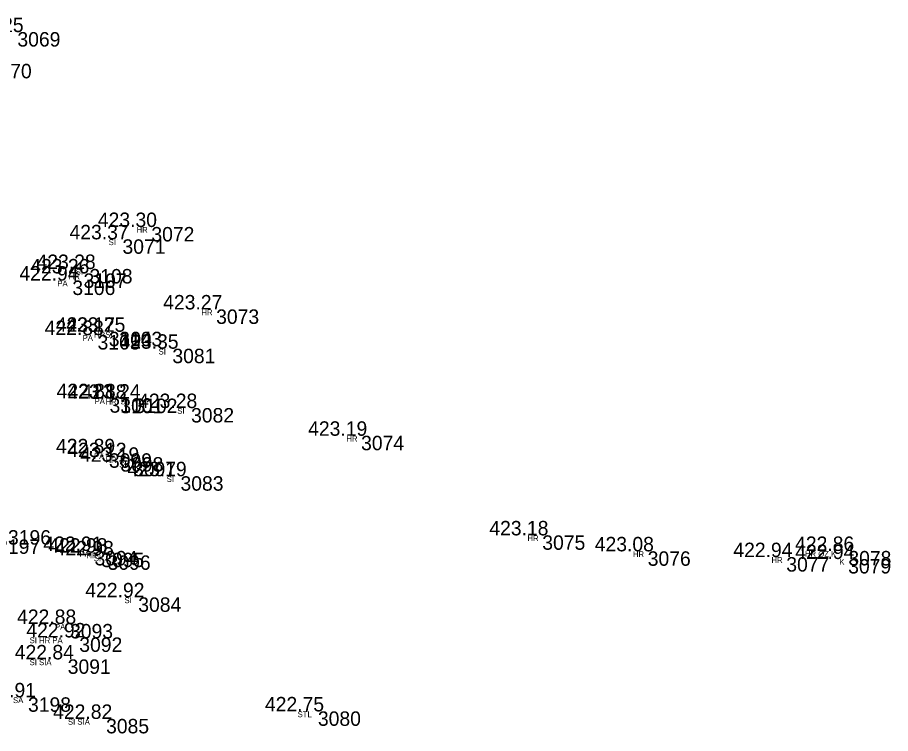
# Model space of a CAD drawing. Extents: x -639390 to -639075, y -1138747 to -1138358.
# Drawn here: x -639135.29 to -639089.99, y -1138616.86 to -1138579.68 of the extents above; entities that cross this region are included whole.
import ezdxf

# ---------------------------------------------------------------- set-up
doc = ezdxf.new("R2010")
doc.units = 0
for name, color, linetype in [('Vrstva 11', 7, 'Continuous'), ('Vrstva 12', 7, 'Continuous'), ('Vrstva 13', 7, 'Continuous'), ('Vrstva 57', 7, 'Continuous')]:
    doc.layers.add(name, color=color, linetype=linetype)

msp = doc.modelspace()

# ---------------------------------------------------------------- linework, layer by layer
at = {"layer": 'Vrstva 11'}
for p, q in [((-639128.62, -1138590.56), (-639128.62, -1138590.56)), ((-639130.12, -1138591.2), (-639130.12, -1138591.2)), ((-639131.83, -1138592.74), (-639131.83, -1138592.74)), ((-639132.72, -1138593.34), (-639132.72, -1138593.34)), ((-639132.14, -1138592.97), (-639132.14, -1138592.97)), ((-639125.26, -1138594.84), (-639125.26, -1138594.84)), ((-639130.83, -1138596), (-639130.83, -1138596)), ((-639130.29, -1138596), (-639130.29, -1138596)), ((-639131.41, -1138596.17), (-639131.41, -1138596.17)), ((-639127.53, -1138596.88), (-639127.53, -1138596.88)), ((-639130.79, -1138599.45), (-639130.79, -1138599.45)), ((-639130.23, -1138599.48), (-639130.23, -1138599.48)), ((-639129.5, -1138599.47), (-639129.5, -1138599.47)), ((-639126.56, -1138599.96), (-639126.56, -1138599.96)), ((-639117.74, -1138601.4), (-639117.74, -1138601.4)), ((-639130.82, -1138602.31), (-639130.82, -1138602.31)), ((-639130.23, -1138602.51), (-639130.23, -1138602.51)), ((-639129.57, -1138602.75), (-639129.57, -1138602.75)), ((-639127.11, -1138603.5), (-639127.11, -1138603.5)), ((-639108.34, -1138606.57), (-639108.34, -1138606.57)), ((-639131.57, -1138607.38), (-639131.57, -1138607.38)), ((-639102.87, -1138607.4), (-639102.87, -1138607.4)), ((-639092.46, -1138607.38), (-639092.46, -1138607.38)), ((-639131.22, -1138607.47), (-639131.22, -1138607.47)), ((-639130.89, -1138607.61), (-639130.89, -1138607.61)), ((-639095.68, -1138607.7), (-639095.68, -1138607.7)), ((-639092.47, -1138607.8), (-639092.47, -1138607.8)), ((-639129.3, -1138609.79), (-639129.3, -1138609.79)), ((-639132.84, -1138611.17), (-639132.84, -1138611.17)), ((-639132.36, -1138611.87), (-639132.36, -1138611.87)), ((-639132.96, -1138613.01), (-639132.96, -1138613.01)), ((-639135.02, -1138614.98), (-639135.02, -1138614.98)), ((-639119.98, -1138615.71), (-639119.98, -1138615.71)), ((-639130.97, -1138616.1), (-639130.97, -1138616.1))]:
    msp.add_line(p, q, dxfattribs=at)

# ---------------------------------------------------------------- texts
at = {"layer": 'Vrstva 12'}
for s, p in [('423.25 ', (-639138.04, -1138580.44)), ('423.30 ', (-639131.119, -1138590.56)), ('423.37 ', (-639132.589, -1138591.2)), ('423.28 ', (-639134.299, -1138592.74)), ('423.26 ', (-639134.626, -1138592.97)), ('422.94 ', (-639135.189, -1138593.34)), ('423.27 ', (-639127.729, -1138594.84)), ('422.88 ', (-639133.879, -1138596.17)), ('423.17 ', (-639133.299, -1138596)), ('423.25 ', (-639132.76, -1138596)), ('423.35 ', (-639130, -1138596.88)), ('422.88 ', (-639133.259, -1138599.45)), ('423.18 ', (-639132.699, -1138599.48)), ('423.24 ', (-639131.969, -1138599.47)), ('423.28 ', (-639129.029, -1138599.96)), ('423.19 ', (-639120.209, -1138601.4)), ('422.89 ', (-639133.289, -1138602.31)), ('423.12 ', (-639132.699, -1138602.51)), ('423.19 ', (-639132.039, -1138602.75)), ('423.19 ', (-639129.579, -1138603.5)), ('423.18 ', (-639110.809, -1138606.57)), ('422.91 ', (-639133.945, -1138607.38)), ('422.98 ', (-639133.689, -1138607.47)), ('422.98 ', (-639133.359, -1138607.61)), ('423.08 ', (-639105.339, -1138607.4)), ('422.94 ', (-639098.149, -1138607.7)), ('422.86 ', (-639094.946, -1138607.38)), ('422.94 ', (-639094.939, -1138607.8)), ('422.92 ', (-639131.769, -1138609.79)), ('422.88 ', (-639135.309, -1138611.17)), ('422.92 ', (-639134.829, -1138611.87)), ('422.84 ', (-639135.429, -1138613.01)), ('422.91 ', (-639137.395, -1138614.98)), ('422.75 ', (-639122.45, -1138615.71)), ('422.82 ', (-639133.439, -1138616.1))]:
    msp.add_text(s, height=0.75, dxfattribs=at).set_placement(p)
at = {"layer": 'Vrstva 13'}
for s, p in [(' 3069', (-639135.57, -1138581.19)), (' 3070', (-639137.06, -1138582.84)), (' 3072', (-639128.62, -1138591.31)), (' 3071', (-639130.12, -1138591.95)), (' 3108', (-639131.83, -1138593.49)), (' 3106', (-639132.72, -1138594.09)), (' 3107', (-639132.14, -1138593.72)), (' 3073', (-639125.26, -1138595.59)), (' 3104', (-639130.83, -1138596.75)), (' 3103', (-639130.29, -1138596.75)), (' 3105', (-639131.41, -1138596.92)), (' 3081', (-639127.53, -1138597.63)), (' 3100', (-639130.79, -1138600.2)), (' 3101', (-639130.23, -1138600.23)), (' 3102', (-639129.5, -1138600.22)), (' 3082', (-639126.56, -1138600.71)), (' 3074', (-639117.74, -1138602.15)), (' 3099', (-639130.82, -1138603.06)), (' 3098', (-639130.23, -1138603.26)), (' 3097', (-639129.57, -1138603.5)), (' 3083', (-639127.11, -1138604.25)), (' 3196', (-639136.06, -1138607.05)), (' 3197', (-639136.62, -1138607.53)), (' 3075', (-639108.34, -1138607.32)), (' 3094', (-639131.57, -1138608.13)), (' 3076', (-639102.87, -1138608.15)), (' 3078', (-639092.46, -1138608.13)), (' 3095', (-639131.22, -1138608.22)), (' 3096', (-639130.89, -1138608.36)), (' 3077', (-639095.68, -1138608.45)), (' 3079', (-639092.47, -1138608.55)), (' 3084', (-639129.3, -1138610.54)), (' 3093', (-639132.84, -1138611.92)), (' 3092', (-639132.36, -1138612.62)), (' 3091', (-639132.96, -1138613.76)), (' 3198', (-639135.02, -1138615.73)), (' 3080', (-639119.98, -1138616.46)), (' 3085', (-639130.97, -1138616.85))]:
    msp.add_text(s, height=0.75, dxfattribs=at).set_placement(p)
at = {"layer": 'Vrstva 57'}
for s, p in [('HR', (-639129.109, -1138590.86)), ('SI', (-639130.558, -1138591.5)), ('SI', (-639132.268, -1138593.04)), ('PA', (-639133.22, -1138593.64)), ('HR', (-639132.629, -1138593.27)), ('HR', (-639125.749, -1138595.14)), ('HR', (-639131.319, -1138596.3)), ('SI', (-639130.728, -1138596.3)), ('PA', (-639131.91, -1138596.47)), ('SI', (-639127.968, -1138597.18)), ('PA', (-639131.29, -1138599.75)), ('HR', (-639130.719, -1138599.78)), ('SI', (-639129.938, -1138599.77)), ('SI', (-639126.998, -1138600.26)), ('HR', (-639118.229, -1138601.7)), ('PA', (-639131.32, -1138602.61)), ('HR', (-639130.719, -1138602.81)), ('SI', (-639130.008, -1138603.05)), ('SI', (-639127.548, -1138603.8)), ('HR', (-639108.829, -1138606.87)), ('PA', (-639132.07, -1138607.68)), ('HR', (-639103.359, -1138607.7)), ('HR OZ K', (-639094.435, -1138607.68)), ('HR', (-639131.709, -1138607.77)), ('SI', (-639131.328, -1138607.91)), ('HR', (-639096.169, -1138608)), ('K', (-639092.645, -1138608.1)), ('SI', (-639129.738, -1138610.09)), ('PA', (-639133.34, -1138611.47)), ('SI HR PA', (-639134.66, -1138612.17)), ('SI SIA', (-639134.66, -1138613.31)), ('SA', (-639135.52, -1138615.28)), ('STL', (-639120.755, -1138616.01)), ('SI SIA', (-639132.67, -1138616.4))]:
    msp.add_text(s, height=0.3, dxfattribs=at).set_placement(p)

doc.saveas('drawing.dxf')
